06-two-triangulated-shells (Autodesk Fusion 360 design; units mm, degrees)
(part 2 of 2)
sketch "B Facet 180 Triangle 4" plane through (0, -75, 0) normal (0, -1, 0) x axis (-1, 0, 0)
  line L1 (124, -27.066) -> (60.9665, 27.066)
  line L2 (124, 27.066) -> (124, -27.066)
  line L3 (60.9665, 27.066) -> (124, 27.066)
  line L4 (120, -18.3583) -> (71.7639, 23.066)
  line L5 (120, 23.066) -> (120, -18.3583)
  line L6 (71.7639, 23.066) -> (120, 23.066)
  point P1 (0, 0)
  point P2 (60.9665, 27.066)
  point P3 (124, -27.066)
  point P4 (124, 27.066)
  dimension "d486" distance P1 P2 = 60.9665 (= "Linear Dimension-2")
  dimension "d487" distance P1 P2 = 27.066 (= "Linear Dimension-3")
  dimension "d488" distance P1 P3 = 124 (= "Linear Dimension-4")
  dimension "d489" distance P1 P3 = 27.066 (= "Linear Dimension-5")
  dimension "d490" distance P1 P4 = 124 (= "Linear Dimension-6")
  dimension "d491" distance P1 P4 = 27.066 (= "Linear Dimension-7")
  dimension "d492" = -4 (= "-memberWidth / 2")
extrude "Extrude15" cut sketch "B Facet 180 Triangle 4" profile of L5 L6 L4 against normal blind 4.7 (magnitude of "-( wall + 0.2 mm )")
fillet "Fillet5" radius 1.5 (= "apertureRadius")
work_plane "WorkPlane11" RotateAngle 135 ExtraOffset 0
work_plane "WorkPlane12" AlongDistance 75 (= "bodyWidth / 2") ExtraOffset 0
sketch "B Facet 225 Triangle 1" plane through (0, -53.033, -53.033) normal (0, -0.7071, -0.7071) x axis (1, 0, 0)
  line L1 (23.9949, -27.066) -> (62.2721, 27.066)
  line L2 (0.1814, 27.066) -> (23.9949, -27.066)
  line L3 (62.2721, 27.066) -> (0.1814, 27.066)
  line L4 (24.81, -18.9852) -> (54.5447, 23.066)
  line L5 (6.311, 23.066) -> (24.81, -18.9852)
  line L6 (54.5447, 23.066) -> (6.311, 23.066)
  point P1 (0, 0)
  point P2 (62.2721, 27.066)
  point P3 (23.9949, -27.066)
  point P4 (0.1814, 27.066)
  dimension "d501" distance P1 P2 = 62.2721 (= "Linear Dimension-2")
  dimension "d502" distance P1 P2 = 27.066 (= "Linear Dimension-3")
  dimension "d503" distance P1 P3 = 23.9949 (= "Linear Dimension-4")
  dimension "d504" distance P1 P3 = 27.066 (= "Linear Dimension-5")
  dimension "d505" distance P1 P4 = 0.1814 (= "Linear Dimension-6")
  dimension "d506" distance P1 P4 = 27.066 (= "Linear Dimension-7")
  dimension "d507" = 4 (= "memberWidth / 2")
extrude "Extrude16" cut sketch "B Facet 225 Triangle 1" profile of L5 L6 L4 against normal blind 4.7 (magnitude of "-( wall + 0.2 mm )")
sketch "B Facet 225 Triangle 2" plane through (0, -53.033, -53.033) normal (0, -0.7071, -0.7071) x axis (1, 0, 0)
  line L1 (0.1814, 27.066) -> (23.9949, -27.066)
  line L2 (-74.6684, -27.066) -> (0.1814, 27.066)
  line L3 (23.9949, -27.066) -> (-74.6684, -27.066)
  line L4 (-1.4863, 20.9235) -> (17.8653, -23.066)
  line L5 (-62.3117, -23.066) -> (-1.4863, 20.9235)
  line L6 (17.8653, -23.066) -> (-62.3117, -23.066)
  point P1 (0, 0)
  point P2 (23.9949, -27.066)
  point P3 (0.1814, 27.066)
  point P4 (-74.6684, -27.066)
  dimension "d510" distance P1 P2 = 23.9949 (= "Linear Dimension-2")
  dimension "d511" distance P1 P2 = 27.066 (= "Linear Dimension-3")
  dimension "d512" distance P1 P3 = 0.1814 (= "Linear Dimension-4")
  dimension "d513" distance P1 P3 = 27.066 (= "Linear Dimension-5")
  dimension "d514" distance P1 P4 = 74.6684 (= "Linear Dimension-6")
  dimension "d515" distance P1 P4 = 27.066 (= "Linear Dimension-7")
  dimension "d516" = -4 (= "-memberWidth / 2")
extrude "Extrude17" cut sketch "B Facet 225 Triangle 2" profile of L5 L6 L4 against normal blind 4.7 (magnitude of "-( wall + 0.2 mm )")
sketch "B Facet 225 Triangle 3" plane through (0, -53.033, -53.033) normal (0, -0.7071, -0.7071) x axis (1, 0, 0)
  line L1 (-74.6684, -27.066) -> (0.1814, 27.066)
  line L2 (-124, 27.066) -> (-74.6684, -27.066)
  line L3 (0.1814, 27.066) -> (-124, 27.066)
  line L4 (-74.1179, -21.7315) -> (-12.1753, 23.066)
  line L5 (-114.9429, 23.066) -> (-74.1179, -21.7315)
  line L6 (-12.1753, 23.066) -> (-114.9429, 23.066)
  point P1 (0, 0)
  point P2 (0.1814, 27.066)
  point P3 (-74.6684, -27.066)
  point P4 (-124, 27.066)
  dimension "d519" distance P1 P2 = 0.1814 (= "Linear Dimension-2")
  dimension "d520" distance P1 P2 = 27.066 (= "Linear Dimension-3")
  dimension "d521" distance P1 P3 = 74.6684 (= "Linear Dimension-4")
  dimension "d522" distance P1 P3 = 27.066 (= "Linear Dimension-5")
  dimension "d523" distance P1 P4 = 124 (= "Linear Dimension-6")
  dimension "d524" distance P1 P4 = 27.066 (= "Linear Dimension-7")
  dimension "d525" = 4 (= "memberWidth / 2")
extrude "Extrude18" cut sketch "B Facet 225 Triangle 3" profile of L5 L6 L4 against normal blind 4.7 (magnitude of "-( wall + 0.2 mm )")
sketch "B Facet 225 Triangle 4" plane through (0, -53.033, -53.033) normal (0, -0.7071, -0.7071) x axis (1, 0, 0)
  line L1 (-124, 27.066) -> (-74.6684, -27.066)
  line L2 (-124, -27.066) -> (-124, 27.066)
  line L3 (-74.6684, -27.066) -> (-124, -27.066)
  line L4 (-120, 16.7383) -> (-83.7255, -23.066)
  line L5 (-120, -23.066) -> (-120, 16.7383)
  line L6 (-83.7255, -23.066) -> (-120, -23.066)
  point P1 (0, 0)
  point P2 (-74.6684, -27.066)
  point P3 (-124, 27.066)
  point P4 (-124, -27.066)
  dimension "d528" distance P1 P2 = 74.6684 (= "Linear Dimension-2")
  dimension "d529" distance P1 P2 = 27.066 (= "Linear Dimension-3")
  dimension "d530" distance P1 P3 = 124 (= "Linear Dimension-4")
  dimension "d531" distance P1 P3 = 27.066 (= "Linear Dimension-5")
  dimension "d532" distance P1 P4 = 124 (= "Linear Dimension-6")
  dimension "d533" distance P1 P4 = 27.066 (= "Linear Dimension-7")
  dimension "d534" = -4 (= "-memberWidth / 2")
extrude "Extrude19" cut sketch "B Facet 225 Triangle 4" profile of L5 L6 L4 against normal blind 4.7 (magnitude of "-( wall + 0.2 mm )")
fillet "Fillet6" radius 1.5 (= "apertureRadius")
work_plane "WorkPlane13" RotateAngle 180 ExtraOffset 0
work_plane "WorkPlane14" AlongDistance 75 (= "bodyWidth / 2") ExtraOffset 0
sketch "B Facet 270 Triangle 1" plane through (0, 0, -75) normal (0, 0, -1) x axis (-1, 0, 0)
  line L1 (36.9655, 27.066) -> (-17.1665, -27.066)
  line L2 (53.4167, -27.066) -> (36.9655, 27.066)
  line L3 (-17.1665, -27.066) -> (53.4167, -27.066)
  line L4 (35.0777, 19.5214) -> (-7.5097, -23.066)
  line L5 (48.0205, -23.066) -> (35.0777, 19.5214)
  line L6 (-7.5097, -23.066) -> (48.0205, -23.066)
  point P1 (0, 0)
  point P2 (-17.1665, -27.066)
  point P3 (36.9655, 27.066)
  point P4 (53.4167, -27.066)
  dimension "d543" distance P1 P2 = 17.1665 (= "Linear Dimension-2")
  dimension "d544" distance P1 P2 = 27.066 (= "Linear Dimension-3")
  dimension "d545" distance P1 P3 = 36.9655 (= "Linear Dimension-4")
  dimension "d546" distance P1 P3 = 27.066 (= "Linear Dimension-5")
  dimension "d547" distance P1 P4 = 53.4167 (= "Linear Dimension-6")
  dimension "d548" distance P1 P4 = 27.066 (= "Linear Dimension-7")
  dimension "d549" = 4 (= "memberWidth / 2")
extrude "Extrude20" cut sketch "B Facet 270 Triangle 1" profile of L5 L6 L4 against normal blind 4.7 (magnitude of "-( wall + 0.2 mm )")
sketch "B Facet 270 Triangle 2" plane through (0, 0, -75) normal (0, 0, -1) x axis (-1, 0, 0)
  line L1 (53.4167, -27.066) -> (36.9655, 27.066)
  line L2 (124, 27.066) -> (53.4167, -27.066)
  line L3 (36.9655, 27.066) -> (124, 27.066)
  line L4 (55.5648, -20.3777) -> (42.3618, 23.066)
  line L5 (112.2115, 23.066) -> (55.5648, -20.3777)
  line L6 (42.3618, 23.066) -> (112.2115, 23.066)
  point P1 (0, 0)
  point P2 (36.9655, 27.066)
  point P3 (53.4167, -27.066)
  point P4 (124, 27.066)
  dimension "d552" distance P1 P2 = 36.9655 (= "Linear Dimension-2")
  dimension "d553" distance P1 P2 = 27.066 (= "Linear Dimension-3")
  dimension "d554" distance P1 P3 = 53.4167 (= "Linear Dimension-4")
  dimension "d555" distance P1 P3 = 27.066 (= "Linear Dimension-5")
  dimension "d556" distance P1 P4 = 124 (= "Linear Dimension-6")
  dimension "d557" distance P1 P4 = 27.066 (= "Linear Dimension-7")
  dimension "d558" = -4 (= "-memberWidth / 2")
extrude "Extrude21" cut sketch "B Facet 270 Triangle 2" profile of L5 L6 L4 against normal blind 4.7 (magnitude of "-( wall + 0.2 mm )")
sketch "B Facet 270 Triangle 3" plane through (0, 0, -75) normal (0, 0, -1) x axis (-1, 0, 0)
  line L1 (124, 27.066) -> (53.4167, -27.066)
  line L2 (124, -27.066) -> (124, 27.066)
  line L3 (53.4167, -27.066) -> (124, -27.066)
  line L4 (120, 18.9574) -> (65.2053, -23.066)
  line L5 (120, -23.066) -> (120, 18.9574)
  line L6 (65.2053, -23.066) -> (120, -23.066)
  point P1 (0, 0)
  point P2 (53.4167, -27.066)
  point P3 (124, 27.066)
  point P4 (124, -27.066)
  dimension "d561" distance P1 P2 = 53.4167 (= "Linear Dimension-2")
  dimension "d562" distance P1 P2 = 27.066 (= "Linear Dimension-3")
  dimension "d563" distance P1 P3 = 124 (= "Linear Dimension-4")
  dimension "d564" distance P1 P3 = 27.066 (= "Linear Dimension-5")
  dimension "d565" distance P1 P4 = 124 (= "Linear Dimension-6")
  dimension "d566" distance P1 P4 = 27.066 (= "Linear Dimension-7")
  dimension "d567" = 4 (= "memberWidth / 2")
extrude "Extrude22" cut sketch "B Facet 270 Triangle 3" profile of L5 L6 L4 against normal blind 4.7 (magnitude of "-( wall + 0.2 mm )")
fillet "Fillet7" radius 1.5 (= "apertureRadius")
work_plane "WorkPlane15" RotateAngle 225 ExtraOffset 0
work_plane "WorkPlane16" AlongDistance 75 (= "bodyWidth / 2") ExtraOffset 0
sketch "B Facet 315 Triangle 1" plane through (0, 53.033, -53.033) normal (0, 0.7071, -0.7071) x axis (1, 0, 0)
  line L1 (-82.0711, -27.066) -> (-43.7939, 27.066)
  line L2 (-124, 27.066) -> (-82.0711, -27.066)
  line L3 (-43.7939, 27.066) -> (-124, 27.066)
  line L4 (-82.2175, -20.3449) -> (-51.5213, 23.066)
  line L5 (-115.8422, 23.066) -> (-82.2175, -20.3449)
  line L6 (-51.5213, 23.066) -> (-115.8422, 23.066)
  point P1 (0, 0)
  point P2 (-43.7939, 27.066)
  point P3 (-82.0711, -27.066)
  point P4 (-124, 27.066)
  dimension "d576" distance P1 P2 = 43.7939 (= "Linear Dimension-2")
  dimension "d577" distance P1 P2 = 27.066 (= "Linear Dimension-3")
  dimension "d578" distance P1 P3 = 82.0711 (= "Linear Dimension-4")
  dimension "d579" distance P1 P3 = 27.066 (= "Linear Dimension-5")
  dimension "d580" distance P1 P4 = 124 (= "Linear Dimension-6")
  dimension "d581" distance P1 P4 = 27.066 (= "Linear Dimension-7")
  dimension "d582" = 4 (= "memberWidth / 2")
extrude "Extrude23" cut sketch "B Facet 315 Triangle 1" profile of L5 L6 L4 against normal blind 4.7 (magnitude of "-( wall + 0.2 mm )")
sketch "B Facet 315 Triangle 2" plane through (0, 53.033, -53.033) normal (0, 0.7071, -0.7071) x axis (1, 0, 0)
  line L1 (-124, 27.066) -> (-82.0711, -27.066)
  line L2 (-124, -27.066) -> (-124, 27.066)
  line L3 (-82.0711, -27.066) -> (-124, -27.066)
  line L4 (-120, 15.3697) -> (-90.2289, -23.066)
  line L5 (-120, -23.066) -> (-120, 15.3697)
  line L6 (-90.2289, -23.066) -> (-120, -23.066)
  point P1 (0, 0)
  point P2 (-82.0711, -27.066)
  point P3 (-124, 27.066)
  point P4 (-124, -27.066)
  dimension "d585" distance P1 P2 = 82.0711 (= "Linear Dimension-2")
  dimension "d586" distance P1 P2 = 27.066 (= "Linear Dimension-3")
  dimension "d587" distance P1 P3 = 124 (= "Linear Dimension-4")
  dimension "d588" distance P1 P3 = 27.066 (= "Linear Dimension-5")
  dimension "d589" distance P1 P4 = 124 (= "Linear Dimension-6")
  dimension "d590" distance P1 P4 = 27.066 (= "Linear Dimension-7")
  dimension "d591" = -4 (= "-memberWidth / 2")
extrude "Extrude24" cut sketch "B Facet 315 Triangle 2" profile of L5 L6 L4 against normal blind 4.7 (magnitude of "-( wall + 0.2 mm )")
fillet "Fillet8" radius 1.5 (= "apertureRadius")
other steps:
base_feature "Base Feature1" bodies "A Housing print"
base_feature "Base Feature1" bodies "B Moving Body print"
create_component "CreateComponent1"
reparent_decal "ReparentDecal1"
remove_body "RemoveBody1"
create_component "CreateComponent2"
reparent_decal "ReparentDecal2"
remove_body "RemoveBody2"
named bodies: "A Housing print", "B Moving Body print"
